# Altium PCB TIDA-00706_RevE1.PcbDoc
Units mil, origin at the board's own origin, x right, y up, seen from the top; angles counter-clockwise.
Board outline 2362.2 x 1377.95 mil, 2 copper layers (Top Layer, Bottom Layer), stack 62 mil thick; 65 components, 35 nets, 166 pads, 49 vias.
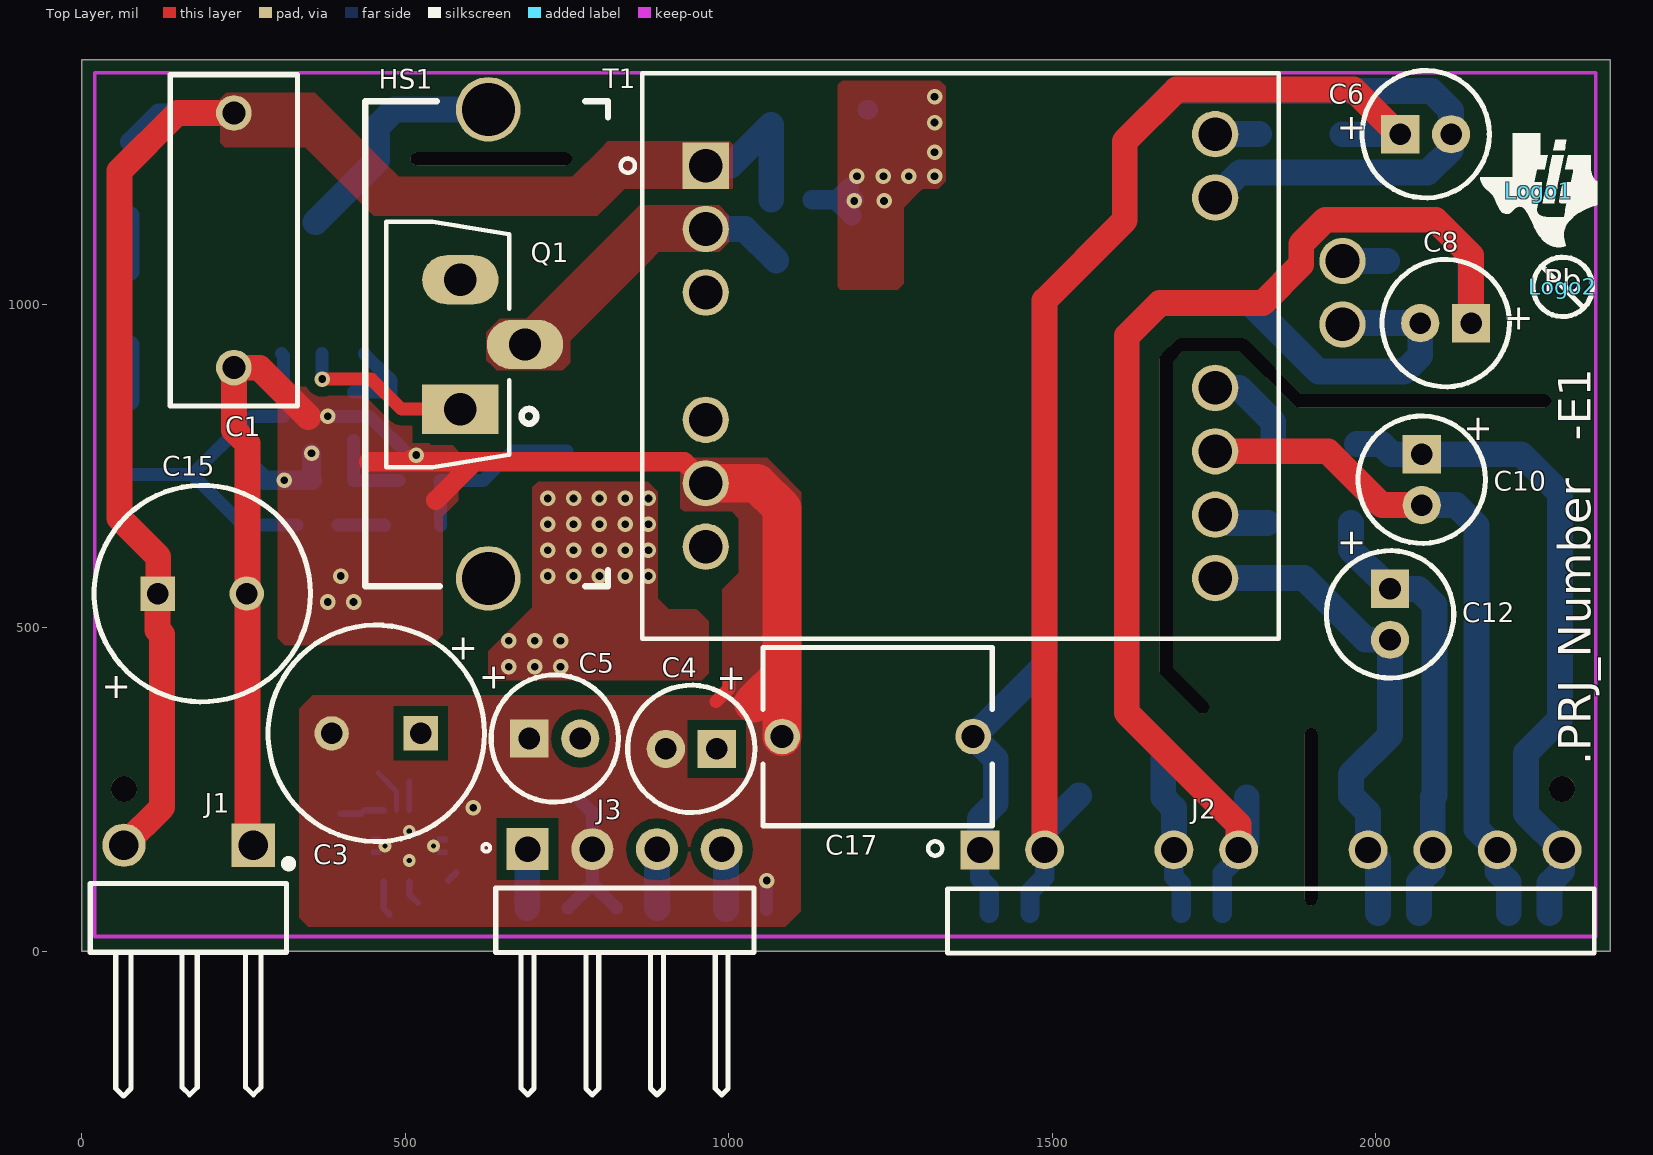
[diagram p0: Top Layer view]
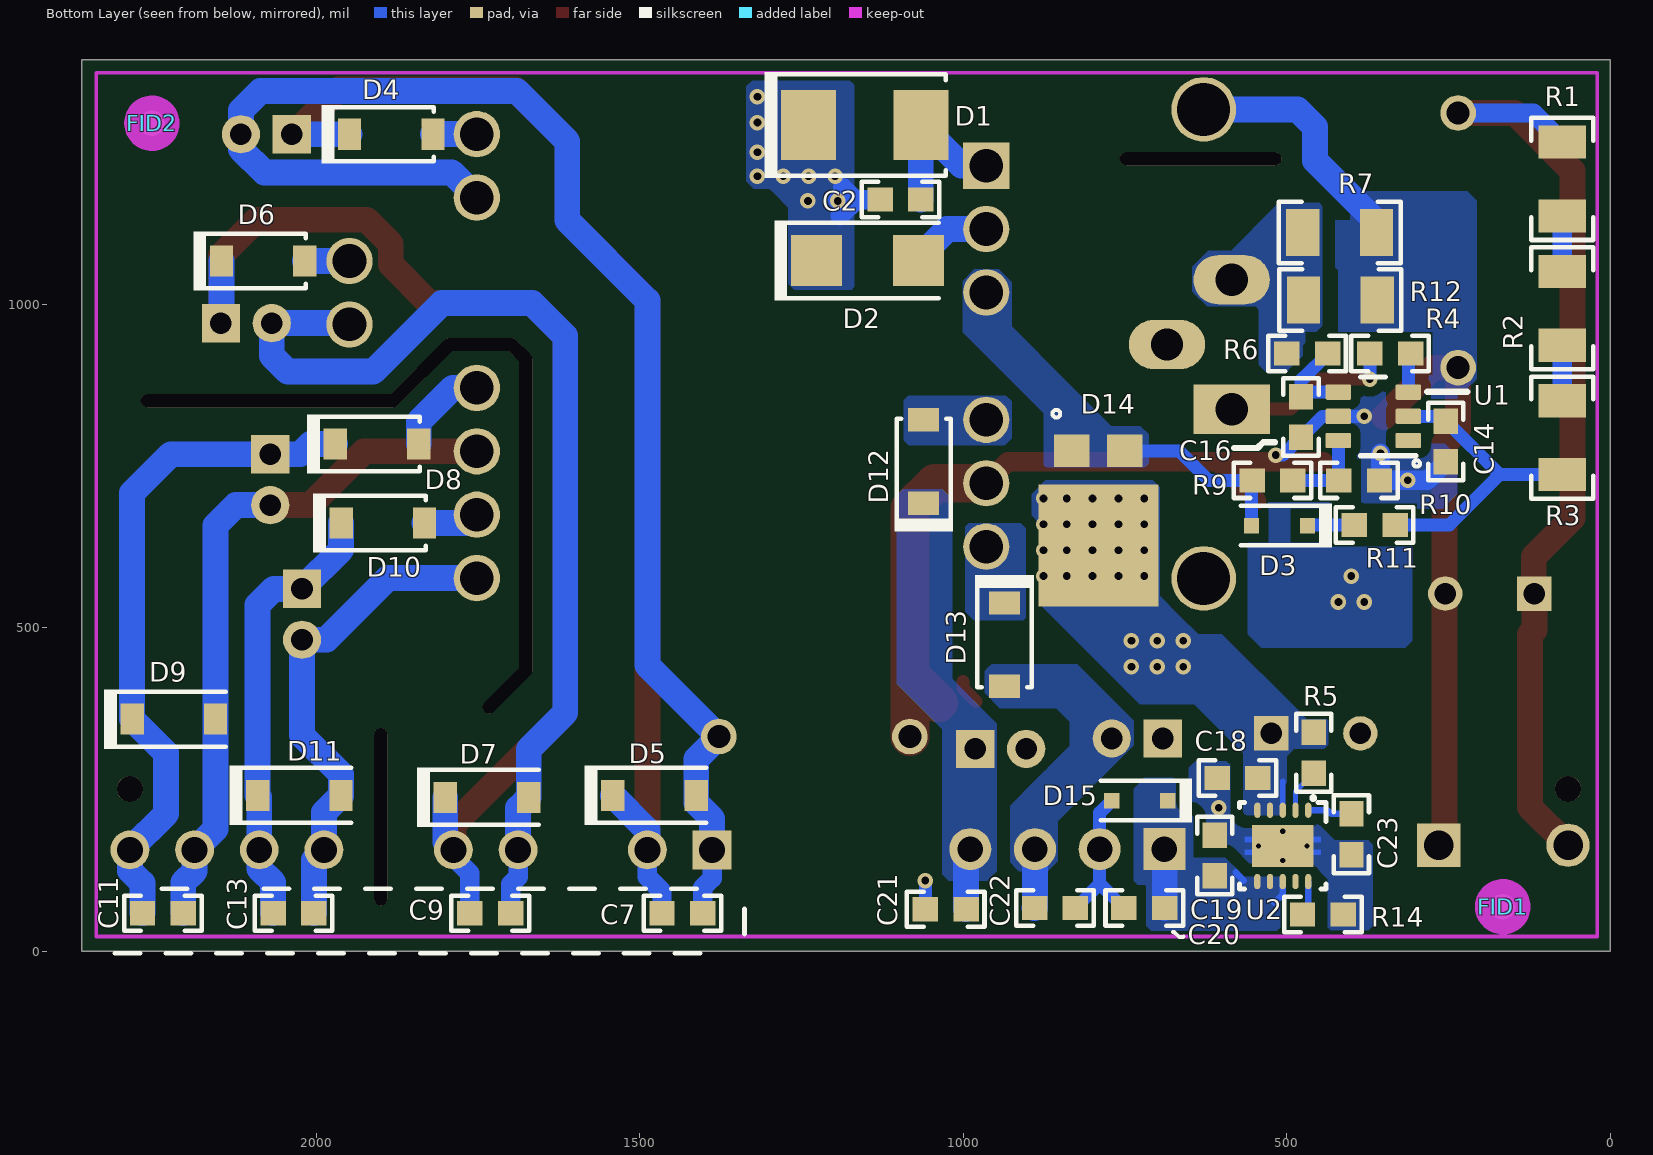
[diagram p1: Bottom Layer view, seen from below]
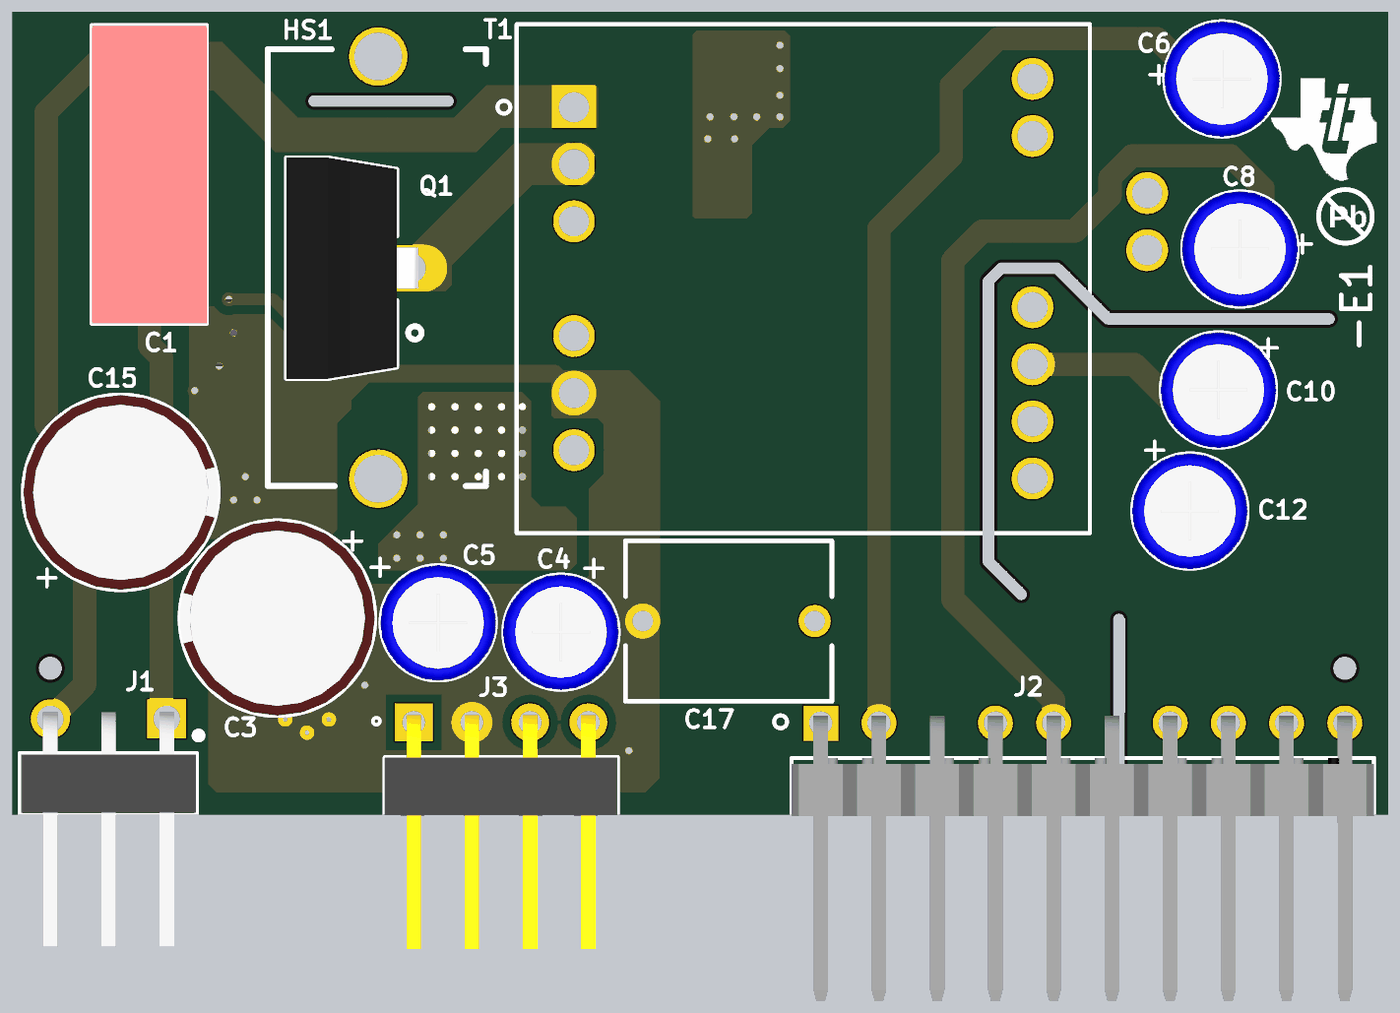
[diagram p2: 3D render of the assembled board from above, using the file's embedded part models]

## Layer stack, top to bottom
Top Solder: solder mask 0.4, Solder Resist, Dk 3.5
Top Layer: signal copper 1.4
Dielectric1: core 59.2, FR-4  High Tg, Dk 4.8
Bottom Layer: signal copper 1.4
Bottom Solder: solder mask 0.4, Solder Resist, Dk 3.5

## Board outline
0,0 0,1377.95 2362.2,1377.95 2362.2,0

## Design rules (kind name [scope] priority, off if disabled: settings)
AcuteAngle [All] p1: minimum=4.50000000000000E+0001 checktracksonly=FALSE
AssemblyTestPointUsage [All] p1: valid=2
Clearance Clearance_1 [ispad vs isvia] p1: gap=8
Clearance Clearance_KEEPOUT [IsKeepOut] p2: gap=3
Clearance Clearance_Poly [InPolygon] p3: gap=15 except(20: Poly-Poly)
Clearance [All] p4: gap=8 except(15: SMDPad-Poly Track-Poly Via-Poly Arc-Poly Fill-Poly THPad-Poly; 20: Poly-Poly)
DiffPairsRouting [All] p1: maxlimit=100 minlimit=10 mostfreqgap=10 toplayer_minwidth=15 toplayer_maxwidth=15 toplayer_prefwidth=15 bottomlayer_minwidth=15 bottomlayer_maxwidth=15 bottomlayer_prefwidth=15 maxuncoupledlength=1000
FabricationTestPointUsage TestPointUsage [All] p1: valid=2 allowmultiple=FALSE
FabricationTestpoint Testpoint [All] p1: side=3 testpointundercomponent=TRUE minsize=40 maxsize=100 preferedsize=60 minholesize=0 maxholesize=40 preferedholesize=32 testpointgrid=1 allowsidetop=TRUE allowsidebottom=TRUE usegrid=TRUE gridtolerance=0.01
FanoutControl Fanout_LCC [IsLCC] p1: bgadir=Out bgaviamode=Centered fanoutstyle=Auto fanoutdirection=Alternating viagrid=1 // Fanout_LCC (Default Rule)
FanoutControl Fanout_BGA [IsBGA] p2: bgadir=Out bgaviamode=Centered fanoutstyle=Auto fanoutdirection=Alternating viagrid=1 // Fanout_BGA (Default Rule)
FanoutControl Fanout_Default [All] p4: bgadir=Out bgaviamode=Centered fanoutstyle=Auto fanoutdirection=Alternating viagrid=1 // Fanout_Default (Default Rule)
FanoutControl Fanout_Small [(CompPinCount < 5)] p5: bgadir=Out bgaviamode=Centered fanoutstyle=Auto fanoutdirection=OutThenIn viagrid=1 // Fanout_Small (Default Rule)
HoleSize [All] p1: absolutevalues=TRUE maxlimit=450 minlimit=8 maxpercent=80.000 minpercent=20.000
MinimumSolderMaskSliver MinimumSolderMaskSliver_Logo [InComponentClass('Logo') vs InComponentClass('Logo')] p1: minsoldermaskwidth=0.7
MinimumSolderMaskSliver [All] p2: minsoldermaskwidth=3.94
PlaneConnect [All] p1: planeconnectstyle=Direct reliefexpansion=10 reliefentries=4 reliefconductorwidth=10 reliefairgap=10
PolygonConnect [All] p1: connectstyle=Direct reliefconductorwidth=10 reliefentries=4 polygonreliefangle="90 Angle" airgapwidth=10
RoutingVias ThermalPadVias [IsVia and InAnyComponent] p1: holewidth=7.87 width=19.68 viastyle="Through Hole" minholewidth=7.87 minwidth=19.68 maxholewidth=12.99 maxwidth=23.62
RoutingVias [All] p2: holewidth=12 width=24 viastyle="Through Hole" minholewidth=10 minwidth=20 maxholewidth=16 maxwidth=32
SilkToBoardRegionClearance [Not ((IsComment or IsDesignator) And (Hide <> 'False')) and not InRegion(1000,500,4000,800)] p1:
SilkToSilkClearance SilkToSilkClearance_Pb-FreeLogo [(HasFootprint('Pb-Free_Overlay_Medium') OR HasFootprint('Pb-Free_Overlay_Small')) vs (HasFootprint('Pb-Free_Overlay_Medium') OR HasFootprint('Pb-Free_Overlay_Small'))] p1: silktosilkclearance=0
SilkToSilkClearance [All] p2: silktosilkclearance=4
SilkToSolderMaskClearance SilkToComonentPadClearance [IsPad and InAnycomponent] p1: minsilkscreentomaskgap=5 clearancetoexposedcopper=TRUE
SilkToSolderMaskClearance "Silk to Solder Mask Opening" [All] p2: minsilkscreentomaskgap=4 clearancetoexposedcopper=FALSE
SolderMaskExpansion [All] p1: expansion=2.5
UnpouredPolygon [All] p1: allowunpoured=FALSE
Width [All] p1: maxlimit=120 minlimit=6 preferedwidth=20 checkconnectedcopper=TRUE
15 further rules are at their usual default settings.

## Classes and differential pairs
component class Header: J1
component class TIDA-00706_Schematics: C1 C2 C3 C4 C5 C6 C7 C8 C9 C10 C11 C12 C13 C14 C15 C16 C17 C18 C19 C20 C21 C22 C23 D1 D2 D3 D4 D5 D6 D7 D8 D9 D10 D11 D12 D13 D14 D15 HS1 J1 J2 J3 Q1 R1 R2 R3 R4 R5 R6 R7 R9 R10 R11 R12 R14 T1 U1 U2
component class AssemblyNote: ZZ2 ZZ3 ZZ4
component class FiducialMark: FID1 FID2
component class TIDA-00706_Hardware: FID1 FID2 Logo1 Logo2 ZZ2 ZZ3 ZZ4
component class Logo: Logo1

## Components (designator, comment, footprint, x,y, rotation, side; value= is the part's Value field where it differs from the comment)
C1 "B32671P6104K" WCAP-FTXX_P10PL20_13x5x11 235,1099 r270 top
C2 "C0603Y472K2RAC7867" 0603 1097,1162 r0 bottom
C3 "EKZN250ELL471MH15D" KZN_800x1150 455,337 r180 top
C4 "25YXJ100M5X11" CAPPR2-5x11 942,313 r180 top
C5 "UPW1E470MDD" CAPPR2-5x11 731,329 r0 top
C6 "25YXJ100M5X11" CAPPR2-5x11 2077,1263 r0 top
C7 "C0603C105K3RACTU" 0603 1434,59 r180 bottom
C8 "25YXJ100M5X11" CAPPR2-5x11 2108,971 r180 top
C9 "C0603C105K3RACTU" 0603 1731,59 r180 bottom
C10 "UPW1E470MDD" CAPPR2-5x11 2071,729 r270 top
C11 "C0603C105K3RACTU" 0603 2237,59 r180 bottom
C12 "25YXJ100M5X11" CAPPR2-5x11 2022,521 r270 top
C13 "C0603C105K3RACTU" 0603 2035,59 r180 bottom
C14 "GRM188R6YA106MA73D" 0603 254,788 r270 bottom
C15 "UVY2W2R2MPD1TD" KZN_800x1150 186,553 r0 top
C16 "GRM1885C1E102JA01D" 0603 478,826 r270 bottom
C17 "CS80ZU2GA222MYNKA" E_900x700x900 1230,332 r0 top locked (schematic designator C35)
C18 "C1608C0G1E472J080AA" 0603 576,268 r0 bottom
C19 "C0603C105K3RACTU" 0603 611,148 r90 bottom
C20 "06033C104JAT2A" 0603 720,67 r0 bottom
C21 "06033C104JAT2A" 0603 1027,65 r0 bottom
C22 "06033C104JAT2A" 0603 858,67 r180 bottom
C23 "GRM1885C1E102JA01D" 0603 400,181 r270 bottom
D1 "SMBJ160A" SMB 1152,1277 r180 bottom
D2 "US1M-13-F" SMA 1148,1068 r180 bottom
D3 "BAS316,115" sod-323 511,658 r0 bottom
D4 "PMEG10020AELRX" SOD-123FL 1884,1263 r180 bottom
D5 "MMSZ4700T1G" SOD-123 1477,241 r180 bottom
D6 "PMEG10020AELRX" SOD-123FL 2082,1067 r180 bottom
D7 "BZT52C9V1-7-F" SOD-123 1736,238 r180 bottom
D8 "PMEG10020AELRX" SOD-123FL 1906,784 r180 bottom
D9 "MMSZ4693T1G" SOD-123 2220,359 r180 bottom
D10 "PMEG10020AELRX" SOD-123FL 1897,662 r180 bottom
D11 "MMSZ5244BT1G" SOD-123 2026,241 r180 bottom
D12 "PMEG10020AELRX" SOD-123FL 1061,757 r90 bottom
D13 "PMEG10020AELRX" SOD-123FL 936,474 r270 bottom
D14 "FSV12100V" TO-277A 791,701.61 r180 bottom
D15 "B0540WS-7" sod-323 727,233 r0 bottom
FID1 "Fiducial" Fiducial10-20 166,69 r180 bottom
FID2 "Fiducial" Fiducial10-20 2254,1280 r180 bottom
HS1 "7173DG" HSINK_7173DG 455,939 r90 top
J1 "PEC03SBAN" Sullins_PEC03SBAN 165,164 r180 top
J2 "PBC10SGBN" SULLINS_PBC10SGBN 1838,47 r180 top locked
J3 "TSW-104-08-G-S-RA" TSW-104-08-G-S-RA 839,158 r0 top (schematic designator J6)
Logo1 "Texas Instruments" TI_Symbol_Overlay_Small 2252,1176 r0 top
Logo2 "Pb-Free Symbol" Pb-Free_Overlay_Small 2289,1027 r0 top
Q1 "AOT7S65L" TO-220_FullPAK_Offset 585,938 r90 top
R1 "CRCW12061M00JNEA" 1206 74,1194 r90 bottom
R2 "CRCW12061M00JNEA" 1206 74,994 r90 bottom
R3 "CRCW12061M00JNEA" 1206 74,794 r90 bottom
R4 "CRCW06030000Z0EA" 0603 340,924 r180 bottom
R5 "CRCW06031M00FKEA" 0603 458,307 r90 bottom
R6 "RC0603FR-07220RL" 0603 468.25,924 r0 bottom
R7 "CRCW12061R24FKEA" 1206 418,1111 r0 bottom
R9 "RC0603FR-0756K2L" 0603 522,728 r0 bottom
R10 "RC0603FR-0725K5L" 0603 388,728 r0 bottom
R11 "CRCW0603100RFKEA" 0603 364,659 r0 bottom
R12 "CRCW12061R24FKEA" 1206 417,1007 r0 bottom
R14 "CRCW060343K2FKEA" 0603 444,57 r0 bottom
T1 "750343154" XFMR_750343154_CUS 1358,920 r0 top locked
U1 "UCC28700DBVR" DBV0006A_N 366,827 r0 bottom
U2 "TPS259241DRCR" DRC0010J 506,163 r270 bottom
ZZ2 "These assemblies are ESD sensitive, ESD precautions shall be observed." AssemblyNote -75,1771.11 r0 top
ZZ3 "These assemblies must be clean and free from flux and all contaminants. Use of no clean flux is not acceptable." AssemblyNote -75,1682.56 r0 top
ZZ4 "These assemblies must comply with workmanship standards IPC-A-610 Class 2, unless otherwise specified." AssemblyNote -75,1594 r0 top

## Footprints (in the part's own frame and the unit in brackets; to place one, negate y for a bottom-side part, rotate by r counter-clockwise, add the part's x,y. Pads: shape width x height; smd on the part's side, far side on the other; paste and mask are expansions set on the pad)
0603 [mm] "0603 from SM-752 data"
  rect 1x0.95 smd: 1(-0.8,0) 2(0.8,0)
  silkscreen extent -1.52,-0.69 1.52,0.69, body extent -0.87,-0.47 0.87,0.47, height 1
1206 [mm] "1206 from SM-752 data"
  rect 1.3x1.85 smd: 1(-1.45,0) 2(1.45,0)
  silkscreen extent -2.4,-1.21 2.4,1.21, body extent -1.7,-0.9 1.7,0.9, height 1.35
AssemblyNote [mil] "Assembly Note"
CAPPR2-5x11 [mm] "Capacitor, Electrolytic, Radial; Body 5 x 11 mm (Dia.xH typ); Pin Spacing 2 mm (typ)"
  rect 1.5x1.5 hole 0.85: 1(-1,0)
  round 1.5 hole 0.85: 2(1,0)
  silkscreen extent -2.5,-2.5 2.5,2.5, body extent -2.53,-2.53 2.53,2.52, height 11.29
DBV0006A_N [mm] "SOT23, 6-Leads, Body 2.9x1.6mm, Pitch 0.95mm, Lead Span 2.8mm, IPC Medium Density"
  rrect17% 1x0.6 smd: 1(-1.375,0.95) 2(-1.375,0) 3(-1.375,-0.95) 4(1.375,-0.95) 5(1.375,0) 6(1.375,0.95)
  silkscreen extent -1.68,-1.55 0.5,1.55, body extent -1.42,-1.46 1.42,1.46, height 1.12
DRC0010J [mm] "SON, 10-Leads, Body 3x3mm, Pitch 0.5mm, Thermal Pad 2.4x1.65mm, TI Recommended"
  oval 0.6x0.24 smd: 1(-1.4,1) 2(-1.4,0.5) 3(-1.4,0) 4(-1.4,-0.5) 5(-1.4,-1) 6(1.4,-1) 7(1.4,-0.5) 8(1.4,0) 9(1.4,0.5) 10(1.4,1)
  rect 1.65x2.4 smd paste-0.825: 11(0,0)
  Top Layer region: 0.135,-1.1 0.365,-1.1 0.365,-1.5 0.135,-1.5
  Top Layer region: -0.135,-1.5 -0.365,-1.5 -0.365,-1.1 -0.135,-1.1
  Top Layer region: -0.135,1.1 -0.365,1.1 -0.365,1.5 -0.135,1.5
  Top Layer region: 0.135,1.5 0.365,1.5 0.365,1.1 0.135,1.1
  silkscreen extent -1.7,-1.7 1.7,1.7, body extent -1.55,-1.55 1.55,1.55, height 1.01
E_900x700x900 [mm] "TH, 2- Leads, Body 9x7mm, Pin Spacing 7.5mm"
  round 1.4 hole 0.9: 1(-3.75,0) 2(3.75,0)
  silkscreen extent -4.5,-3.5 4.5,3.5, body extent -4.49,-3.5 4.49,3.5, height 11.96
Fiducial10-20 [mm]
  round 1 smd mask+0.5: 1(0,0)
  Top Layer keep-out circle w1.178: c0,0 r0.5
HSINK_7173DG [mil] "Aavid"
  round 100 hole 82: 1(-362.5,-173.23) 2(362.5,-173.23)
  silkscreen extent -375,-358 375,17, body extent -375,-358 375,12, height 900
KZN_800x1150 [mm] "TH, 2-Leads, Dia 8mm"
  rect 1.35x1.35 hole 0.85: 1(-1.75,0)
  round 1.35 hole 0.85: 2(1.75,0)
  silkscreen extent -4.25,-4.25 4.25,4.25, body extent -4.22,-4.24 4.24,4.24, height 13.01
Pb-Free_Overlay_Small [mil]
  silkscreen extent -46,-46 46,46
SMA [mm] "Molded Diode, 2-Leads, Body 4.3x2.6mm, IPC Medium Density, based on OnSemi component dimensions and land pattern"
  rect 2x2 smd: 1(-2,0) 2(2,0)
  silkscreen extent -3.66,-1.57 2.79,1.57, body extent -2.6,-1.3 2.6,1.3, height 2.42
SMB [mil] "Molded Diode, 2-Leads, Body 5.4x3.6mm, IPC Medium Density, based on OnSemi component dimensions"
  rect 85x107.99 smd: 1(-87.01,0) 2(87.01,0)
  silkscreen extent -155,-82 125,82, body extent -106,-71 106,71, height 91
SOD-123 [mm] "On Semi recommended land pattern"
  rect 0.915x1.22 smd: 1(-1.637,0) 2(1.637,0)
  silkscreen extent -2.74,-1.17 2.03,1.17, body extent -1.93,-0.9 1.93,0.9, height 1.35
SOD-123FL [mm] "Copied from SOD-123"
  rect 0.915x1.22 smd: 1(-1.637,0) 2(1.637,0)
  silkscreen extent -2.74,-1.16 1.68,1.16, body extent -1.9,-0.9 1.9,0.9, height 1
sod-323 [mm] "NXP recommended land pattern"
  rect 0.6x0.6 smd paste-0.05: 1(-1.1,0) 2(1.1,0)
  silkscreen extent -2.06,-0.86 1.53,0.86, body extent -1.3,-0.67 1.3,0.68, height 1.1
SULLINS_PBC10SGBN [mil] "CONN,MALE-10PIN 2.54MM PITCH,SINGLEROW,SULLINS"
  rect 60x60 / inner round 60 / far side rect 60x60 hole 40: 1(450,-109.84)
  round 60 hole 40: 2(350,-109.84) 4(150,-109.84) 5(50,-109.84) 7(-150,-109.84) 8(-250,-109.84) 9(-350,-109.84) 10(-450,-109.84)
  round 0 all layers, no hole mask+0: 3(250,-109.84) 6(-50,-109.84)
  silkscreen extent -500,-123 530,50, body extent -500,-122 500,368, height 142
Sullins_PEC03SBAN [mm] "Sullins"
  rect 1.7x1.7 hole 1.16: 1(-2.54,0)
  round 0 all layers, no hole mask+0: 2(0,0)
  round 1.7 hole 1.16: 3(2.54,0)
  silkscreen extent -4.07,0.58 3.86,9.85, body extent -3.81,-0.29 3.81,9.94, height 3.56
TI_Symbol_Overlay_Small [mil]
  silkscreen extent -90,-88 91,88
TO-220_FullPAK_Offset [mil] "Infineon  PG-TO220-3-31"
  rect 76x118.11 hole 50: 1(-100,0)
  oval 76x118.11 hole 50: 2(0,-100) 3(100,0)
  silkscreen extent -190,-75 190,115, body extent -190,-112 190,115, height 902
TO-277A [mm] "Vishay"
  rect 1.4x1.27 smd: 1(-1.04,1.83) 2(1.04,1.83)
  rect 4.72x4.8 smd: 3(0,-1.883)
  silkscreen extent -1.8,3.13 -1.5,3.44, body extent -2.35,-4.2 2.4,2.45, height 1.2
TSW-104-08-G-S-RA [mm] "Samtec Right Angle Header"
  rect 1.65x1.65 hole 1: 1(-3.81,0)
  round 1.65 hole 1: 2(-1.27,0) 3(1.27,0) 4(3.81,0)
  silkscreen extent -5.59,-9.65 5.08,0.2, body extent -5.08,-9.91 5.08,0.32, height 3.05
WCAP-FTXX_P10PL20_13x5x11 [mm] "TH, 2-Leads, Body 13x5mm, Pitch 10mm"
  round 1.4 hole 0.9: 1(-5,0) 2(5,0)
  silkscreen extent -6.5,-2.5 6.5,2.5, body extent -6.5,-2.5 6.5,2.5, height 11
XFMR_750343154_CUS [mm] "TRANSFORMER, 2.49 MM PITCH, 14-PIN, 16 MM HEIGHT"
  rect 1.82x1.82 / inner round 1.82 / far side rect 1.82x1.82 hole 1.32: 1(-10,7.48)
  round 1.82 hole 1.32: 2(-10,4.99) 3(-10,2.5) 4(-10,-2.5) 5(-10,-4.99) 6(-10,-7.48) 7(10,-8.715) 8(10,-6.225) 9(10,-3.735) 10(10,-1.245) 11(15,1.245) 12(15,3.735) 13(10,6.225) 14(10,8.715)
  silkscreen extent -13.34,-11.1 12.5,11.1, body extent -12.5,-11.1 12.5,11.1, height 16

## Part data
C1: library part 890334023006, "CAP, Film, 0.1 µF, 630 V, +/- 10%, TH"
C2: library part 06031C472JAT2A, "CAP CER 4700PF 200V X7R 0603"
C3: library part EKZN250ELL271MHB5D, "CAP, AL, 470 µF, 25 V, +/- 20%, 0.075 ohm, TH"
C4 C6 C8 C12: library part UVR1V100MDD1TA, "CAP, AL, 100 µF, 25 V, +/- 20%, TH"
C5 C10: library part UVR1V100MDD1TA, "CAP, AL, 47 µF, 25 V, +/- 20%, TH"
C7 C9 C11 C13: library part C0603C105K8PACTU, "CAP CER 1UF 25V X7R 0603"
C14: library part GRM188R6YA106MA73, "CAP, CERM, 10 µF, 35 V, +/- 20%, X5R, 0603"
C15: library part EKZN250ELL271MHB5D, "CAP ALUM 2.2UF 20% 450V RADIAL"
C16 C23: "CAP, CERM, 1000 pF, 25 V, +/- 5%, C0G/NP0, 0603"
C17: library part DE6E3KJ222MN3A, "CAP CER 2200PF 300VAC 20% RADIAL"
C18: library part 0603ZD475KAT2A, "CAP, CERM, 4.7 µF, 25 V, +/- 10%, 0603"
C19: "CAP, CERM, 1 µF, 25 V, +/- 10%, X7R, 0603"
C20 C21 C22: "CAP, CERM, 0.1 µF, 25 V, +/- 5%, X7R, 0603"
D1: library part SMBJ160A-13-F, "TVS DIODE 160VWM 259VC SMB"
D2: "Diode, Ultrafast, 1000 V, 1 A, SMA"
D3: "Diode, Ultrafast, 100V, 0.25A, SOD-323"
D4 D6 D8 D10 D12 D13: library part MBR1H100SFT3G, "DIODE SCHOTTKY 100V 2A SOD2123"
D5: "Diode, Zener, 13 V, 500 mW, SOD-123"
D7: library part BZT52B9V1-HE3-08, "DIODE ZENER 9.1V 500MW SOD123"
D9: "Diode, Zener, 7.5 V, 500 mW, SOD-123"
D11: library part MMSZ4700T1G, "Diode, Zener, 14 V, 500 mW, SOD-123"
D14: library part SS5P10-M3/86A, "DIODE SCHOTTKY 100V 12A TO277-3"
D15: "Diode, Schottky, 40 V, 0.5 A, SOD-323"
FID1 FID2: "Fiducial mark.  There is nothing to buy or mount."
HS1: "Heat Sink, TO-220 Vertical"
J1: "Header, 100mil, 3x1, Tin, R/A, TH"
J2: "CONNECTOR, HEADER, 2.54MM PITCH, 10 POS, RIGHT ANGLE, TH, ROHS"
J3: "Header, 100mil, 4x1, Gold, R/A, TH"
Logo1: library part TI_Logo, "Texas Instrument Corporate Signature"
Logo2: library part Pb-Free
Q1: library part IPA60R385CP, "MOSFET, N-CH, 650 V, 7 A, TO-220"
R1 R2 R3: "RES, 1.0 M, 5%, 0.25 W, 1206"
R4: "RES, 0, 5%, 0.1 W, 0603"
R5: "RES, 1.00 M, 1%, 0.1 W, 0603"
R6: "RES, 220, 1%, 0.1 W, 0603"
R7 R12: "RES, 1.24, 1%, 0.25 W, 1206"
R9: library part CRCW060310K0FKEA, "RES SMD 56.2K OHM 1% 1/10W 0603"
R10: library part CRCW06034K64FKEA, "RES SMD 25.5K OHM 1% 1/10W 0603"
R11: "RES, 100, 1%, 0.1 W, 0603"
R14: "RES, 43.2 k, 1%, 0.1 W, 0603"
U1: "Constant-Voltage, Constant-Current Controller With Primary-Side Regulation, DBV0006A"
U2: "12-V eFuse with Over Voltage Protection and Blocking FET Control, DRC0010J"
ZZ2 ZZ3 ZZ4: library part AssemblyNote

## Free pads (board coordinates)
  round 40 hole 40 unplated mask+5: 0(65,251) 0(2288,251)
  oval 20x500 hole 20 slot 500 at 90 deg unplated mask+5: 1(1676,676)
  oval 20x50 hole 20 slot 50 at 45 deg unplated rot 135 mask+5: 1(1687,927)
  oval 20x100 hole 20 slot 100 at 135 deg unplated rot 45 mask+5: 1(1704,406)
  oval 115x20 hole 20 slot 115 at 0 deg unplated mask+5: 1(1746,938)
  oval 20x135 hole 20 slot 135 at 135 deg unplated rot 45 mask+5: 1(1837,895)
  oval 400x20 hole 20 slot 400 at 0 deg unplated mask+5: 1(2071,851)
  oval 20x274.02 hole 20 slot 274.02 at 90 deg unplated mask+5: 2(1900,208)
  oval 250x20 hole 20 slot 250 at 0 deg unplated mask+5: 4(633,1225)

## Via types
v1: diameter 24, hole 12, Top Layer to Bottom Layer, tented both sides, 45 vias
v2: diameter 19.68, hole 7.87, Top Layer to Bottom Layer, 4 vias

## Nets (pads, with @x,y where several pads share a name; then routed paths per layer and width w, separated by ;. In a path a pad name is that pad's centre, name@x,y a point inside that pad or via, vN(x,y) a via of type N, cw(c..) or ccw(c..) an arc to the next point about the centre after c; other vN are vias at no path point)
7.2V_ISO/0.1A: C8.1 C9.1 D6.1 D7.1 J2.5 | length 1909.9
  Top Layer w40: J2.5 1788,196 1615,369 1615,951 1666,1002 1825,1002 1884.73,1061.73 1884.73,1093.6 1922,1130.87 2092,1130.87 2147.37,1075.5 C8.1
  Bottom Layer w30: C9.1 1762.5,120.5 1788,146 J2.5
  Bottom Layer w40: J2.5 1800.47,169.31 D7.1 ; D6.1 2146.47,971.9 C8.1
+5V/0.2A: C4.1 C21.1 D12.1 J3.4 | length 95.7
  Bottom Layer w40: J3.4 995.5,151.5 C21.1
+6V_ISO/0.05A: C10.1 C11.1 D8.1 D9.1 J2.10 | length 1047.8
  Bottom Layer w40: D8.1 2009,784 2024.63,768.37 C10.1 2224.63,768.37 2284.47,708.53 D9.1 2232,306.53 2232,212.84 J2.10 2288,125 2268.5,105.5 C11.1
+11V_ISO/0.2A: C6.1 C7.1 D4.1 D5.1 J2.2 | length 1939
  Top Layer w40: J2.2 1488,1006 1612,1130 1612,1252 1692,1332 1965.63,1332 C6.1@2037.63,1260
  Bottom Layer w30: C7.1 1465.5,92.5 1488,115 J2.2
  Bottom Layer w40: J2.2 1488,187.53 D5.1 ; D4.1 2034.63,1263 C6.1@2037.63,1260
+12V/1.5A: C19.1 C20.1 D15.1 J3.1 U2.6 U2.7 U2.8 | length 147.9
  Bottom Layer w10: U2.8 506,88 519,75 ; 566,109 579,122
  Bottom Layer w40: C20.1 688.5,157.5 J3.1
+12V_ISO/0.2A: C12.1 C13.1 D10.1 D11.1 J2.8 | length 691.9
  Bottom Layer w40: D10.1 1961.47,620.9 C12.1 2065.63,560.37 2090.47,535.53 D11.1 2088,238.53 J2.8 2088,128 2066.5,106.5 C13.1
+12V_M: C3.1 C18.1 D14.3 R5.2 U2.3 U2.4 U2.5 | length 44.9
  Bottom Layer w8: U2.3 506,263
  other v1: 660,440 700,440 740,440 660,480 700,480 740,480 720,580 760,580 800,580 840,580 875.65,580 720,620 760,620 800,620 840,620 875.65,620 720,660 760,660 800,660 840,660 875.65,660 720,700 760,700 800,700 840,700 875.65,700
-7.2V/0.05A: C5.2 C22.1 D13.2 J3.3 | length 91.2
  Bottom Layer w40: J3.3 889,67.5 C22.1
NetC2_2: C2.2 D1.1 D2.1 | length 128.6
  Bottom Layer w30: C2.2 1165,1162 ; 1186,1180 1168,1162 ; 1190,1137 1165,1162 ; v1@1194,1162 1168,1162 ; D1.1@1213.5,1301 D1.1@1215.74,1301 ; 1165,1162 1168,1162
  other v1: 1194,1160 1240,1160 1198,1198 1239,1198 1278,1198 1318,1198 1318,1235 1318,1281 1318,1321
NetC16_1: C16.1 R6.1 U1.4 | length 144.8
  Bottom Layer w20: U1.4 471.09,864.4 C16.1 478,882.76 473.46,887.3 472.61,887.3 436.76,923.15 R6.1
NetC23_1: C23.1 U2.1 | length 69
  Bottom Layer w10: C23.1 431.38,212.5 437,218.12 U2.1
NetD2_2: D2.2 Q1.2 T1.2 | length 137
  Bottom Layer w30: T1.2@956.3,1101.46 T1.2@964.3,1101.46
  Bottom Layer w40: T1.2 1024.8,1116.46 D2.2@1073.26,1068
NetD3_1: D3.1 R11.2 | length 72.6
  Bottom Layer w20: R11.2 466.69,659 D3.1
NetD3_2: D3.2 D14.1 D14.2 R9.2 T1.3 | length 285.8
  Bottom Layer w20: D3.2 554.31,727.19 R9.2 620.67,728 666.33,773.66 D14.2
NetD4_2: D4.2 T1.14 | length 67.9
  Bottom Layer w40: T1.14 1819.42,1263.11 D4.2
NetD6_2: D6.2 T1.12 | length 69
  Bottom Layer w40: T1.12 D6.2 D6.2
NetD8_2: D8.2 T1.10 | length 146.1
  Bottom Layer w40: T1.10 1789.02,870.98 1841.53,818.47 D8.2
NetD10_2: D10.2 T1.8 | length 86.2
  Bottom Layer w40: T1.8 1764.62,662 D10.2
NetD12_2: D12.2 T1.4
NetD13_1: D13.1 T1.6
NetQ1_1: Q1.1 R4.1 | length 272.3
  Top Layer w20: v1(371.5,884.5) 447.5,884.5 494,838 Q1.1
  Bottom Layer w20: v1(371.5,884.5) R4.1
NetQ1_3: Q1.3 R6.2 R7.2 R12.2
NetR1_1: R1.1 R2.2 | length 85.8
  Bottom Layer w30: R2.2 R1.1
NetR2_1: R2.1 R3.2 | length 85.8
  Bottom Layer w30: R3.2 R2.1
NetR4_2: R4.2 U1.3 | length 61
  Bottom Layer w20: R4.2 311.86,920.64 U1.3
NetR5_1: R5.1 U2.2 | length 69.1
  Bottom Layer w8: R5.1 486.31,247.19 U2.2
NetR14_2: R14.2 U2.10 | length 54.6
  Bottom Layer w10: U2.10 466.63,65.87 R14.2
PGND: C1.2 C3.2 C4.2 C5.1 C14.2 C15.2 C16.2 C17.1 C18.2 C19.2 C20.2 C21.2 C22.2 C23.2 D15.2 HS1.2 J1.1 J3.2 R7.1 R10.1 R12.1 R14.1 T1.5 U1.5 U2.11 | length 3093.2
  Top Layer w20: v1@506.54,764.98 514.98,764.98 v1(517,767) ; 980,386 1000,406 1000,417
  Top Layer w30: 443,757 607,757 ; 547,697 607,757 ; T1.5 930.84,757 607,757
  Top Layer w40: J1.1 255.9,173.1 255.9,785 235,805.9 C1.2 274.37,902.15 350,826.52 350,826
  Top Layer w60: T1.5 1043.46,723.54 1082.36,684.64 1082.36,428.36 ; 1038,384 1082.36,428.36 ; C17.1 1082.36,428.36
  Bottom Layer w20: v1(380,827) U1.5 444.65,827 477.15,794.5 C16.2 505.5,767 v1(517,767) ; C20.2 789,104.5 ; D15.2 789,214.31 J3.2 789,104.5 ; C22.2 789,104.5 ; C21.2 v1(1058.5,109.5)
  Bottom Layer w30: C14.2 282.5,728 v1(313,728) R10.1 355,729.5 v1(355,770.07)
  Bottom Layer w40: R7.1@360.91,1127 456.46,1222.54 456.46,1274.46 483.5,1301.5 HS1.2
  other v1: 605,222 380,540 420,540 400,580
  other v2: 506,140.36 468.6,163 543.4,163 506,185.64
PGND2: C12.2 C13.2 D11.2 J2.7 T1.7 | length 774.8
  Bottom Layer w40: T1.7 1889.11,576.89 1984.37,481.63 C12.2 2022,334 1961.53,273.53 D11.2 1988,214.53 J2.7 2003.5,141.34 C13.2
PGND3: C10.2 C11.2 D9.2 J2.9 T1.9 | length 1071.4
  Top Layer w40: T1.9 1926.05,772.95 2009.37,689.63 C10.2
  Bottom Layer w40: C10.2 2124.37,689.63 2155.53,658.47 D9.2 2155.53,189.31 J2.9 2188,124 2205.5,106.5 C11.2
SGND1: C8.2 C9.2 D7.2 J2.4 T1.11 | length 1627.1
  Bottom Layer w30: J2.4 1688,115 1699.5,103.5 C9.2
  Bottom Layer w40: J2.4 1688,221.53 D7.2 1671.53,312.47 1615,369 1615,951 1666,1002 1806,1002 1912,896 2044,896 2068.63,920.63 C8.2 1950.54,971 T1.11
SGND2: C6.2 C7.2 C17.2 D5.2 J2.1 T1.13 | length 2325.2
  Bottom Layer w30: J2.1 1388,113 1402.5,98.5 C7.2
  Bottom Layer w40: J2.1 1388,205 1412.53,229.53 D5.2 1412.53,297.11 C17.2 1488,442.36 1488,1006 1612,1130 1612,1252 1690,1330 2086,1330 2116.37,1299.63 C6.2 2116.37,1240.09 2080.28,1204 1790.62,1204 T1.13
VDCBUS: C1.1 C2.1 C15.1 D1.2 J1.3 R1.2 T1.1 | length 1737.7
  Top Layer w40: J1.3 124,223 124,490 117.1,496.9 C15.1 ; C15.1@118.1,553 118.1,609.9 58,670 58,1206 147.85,1295.85 C1.1
  Bottom Layer w30: R1.2 118.76,1295.85 C1.1 ; T1.1@956.3,1199.49 T1.1@964.3,1199.49
  Bottom Layer w40: T1.1 1002.48,1214.49 D1.2 1065.5,1276.49 C2.1
VDD: C14.1 R3.1 R11.1 U1.2 | length 469.4
  Bottom Layer w20: R3.1 170.57,736.91 ; U1.2 261.5,827 C14.1 253.15,819.5 170.57,736.91 ; R11.1 248.48,659 170.57,736.91
VS: R9.1 R10.2 U1.6 | length 132.9
  Bottom Layer w20: U1.6 420.13,728.64 R10.2 R9.1
pads on no net: FID1.1 FID2.1 HS1.1 J1.2 J2.3 J2.6 U1.1 U2.9

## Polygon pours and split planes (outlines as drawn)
NetC2_2 on Top Layer "Bottom Layer-No Net 1" (solid, remove dead copper, pour order 36): 1270,1032 1270,1149.5 1293,1172.5 1299.5,1179 1324,1179 1335,1190 1335,1337 1326,1346 1247,1346 1175,1346 1170,1341 1168,1339 1168,1212 1168,1027 1172,1023 1261,1023
PGND on Top Layer "Top Layer-No Net" (solid, remove dead copper, pour order 38): 925,745 925,695 925,685 930,680 980,680 1004.5,680 1015.5,669 1015,668.5 1015,620 1015,585 990,560 990,370 1104,370 1112,378 1112,480 1112,710 1073,749 1059,763 975,763 936.84,763 930.84,757 925,751.16
NetD2_2 on Top Layer "Bottom Layer-No Net 1" (solid, remove dead copper, pour order 34): 646,978 687,978 703,994 862,1153 930,1153 985,1153 1000,1138 1000,1096 985,1081 926,1081 892,1081 877,1066 755,944 755,933 755,910 743,898 718,898 641,898 634,905 625,914 625,916 625,957 633,965
VDCBUS on Top Layer "Bottom Layer-No Net 1" (solid, remove dead copper, pour order 21): 236,1327 223,1327 218,1322 214,1318 214,1301 214,1250 221,1243 268,1243 345,1243 424,1164 451,1137 697,1137 797,1137 818,1158 836,1176 839,1179 1005,1179 1006,1180 1006,1205 1006,1247.46 1002.46,1251 1001.46,1252 977,1252 813,1252 801,1240 758,1197 489.73,1197 414,1273 360,1327 240,1327
PGND on Top Layer "Bottom Layer-No Net 1" (solid, remove dead copper, pour order 27): 303,827.35 303,483.33 305,481.33 313.33,473 338,473 542,473 558,489 558,532 558,672.5 572.5,687 582,696.5 582,732 582,773 573,782 540,782 518,804 510,812 510,851 488.3,872.7 367,873 319.08,873 303,856.92
+12V_M on Top Layer "Bottom Layer-No Net 1" (solid, remove dead copper, pour order 29): 696.51,716 696,715.49 696,534 696,532 672,508 628,464 628,442 628,428 637,419 958,419 969,430 969,456 969,510 954,525 950,529 908,529 907,529 897,539 890.5,545.5 890.5,562 890.5,710.38 880.36,720.53 874.88,726 824,726 705.51,726 696.51,717
PGND on Top Layer "Bottom Layer-No Net 1" (solid, remove dead copper, pour order 24): 336,375 336,284 336,52 350,38 617,38 723,38 1087,38 1108,59 1111,62 1111,227 1111,357 1100,368 1072,396 789,396 357,396
NetD3_2 on Bottom Layer "Top Layer-No Net 2" (solid, remove dead copper, pour order 37): 719,748 865.87,748 871.65,748 875.65,752 875.65,786.35 875.65,831.65 1001,957 1001,1023 1001,1036 983,1054 945,1054 925,1034 925,966 839,880 771,812 726,812 714,800 713,799 713,763 713,754 716,751
+5V/0.2A on Bottom Layer "Bottom Layer-No Net 1" (solid, remove dead copper, pour order 25): 1034,714 1093,714 1103,704 1103,414 1032,343 1032,119 1022,109 992,109 963,109 957,115 948,124 948,352 952,356 1017,421 1017,699 1032,714
NetD12_2 on Bottom Layer "Bottom Layer-No Net 1" (solid, remove dead copper, pour order 28): 952,859 1010,859 1085,859 1092,852 1092,830 1092,798 1092,790 1086,784 1084,782 966,782 936,782 926,792 925,793 925,822 925,850 934,859
NetD13_1 on Bottom Layer "Bottom Layer-No Net 1" (solid, remove dead copper, pour order 30): 926,662 975,662 991,662 1000,653 1003,650 1003,627 1003,531 992,520 984,512 942,512 907,512 903,516 903,654 911,662
NetC2_2 on Bottom Layer "Bottom Layer-No Net 1" (solid, remove dead copper, pour order 35): 1270,1032 1270,1149.5 1293,1172.5 1299.5,1179 1324,1179 1335,1190 1335,1337 1326,1346 1247,1346 1175,1346 1170,1341 1168,1339 1168,1212 1168,1027 1172,1023 1261,1023
+12V/1.5A on Bottom Layer "Top Layer-NetL_1" (solid, remove dead copper, pour order 22): 500,122 499,121 499,100 499,89 499,48 515,32 562,32 627,32 641,32 709,32 736.48,59.48 736.48,191.86 736.48,251.52 720,268 667,268 641.52,242.52 641.52,188 641.52,155.52 636,150 632,146 618,146 596,146 572,122 501,122
+12V_M on Bottom Layer "Top Layer-NetL_1" (solid, remove dead copper, pour order 20): 696.51,717.36 696.51,549.51 666,519 637,490 600,490 480,370 469,359 454,359 438,359 437,358 436,357 436,332 436,319 440,315 442,313 456,313 488.89,313 491.7,310.19 500,301.89 500,300 500,209 505,204 512,204 557,204 561,208 567,214 567,229.93 567,306 598,337 643,382 723,382 727,382 890.5,545.5 894,549 894,570 894,706.88 872.88,728 780,728 707.15,728 696.51,717.36
NetQ1_3 on Bottom Layer "Top Layer-NetL_1" (solid, remove dead copper, pour order 31): 445,1152 445,1101 445,967 448,964 456,956 466,946 475,937 475,917 475,902 480,897 502.25,896.73 532.73,896.73 543,907 543,936 543,988 543,992 548,997 569,997 623,997 642,1016 646,1020 646,1058 621,1083 587,1083 586,1083 519,1150 512,1157 452,1157 450,1157
PGND on Bottom Layer "Top Layer-NetL_1" (solid, remove dead copper, pour order 26): 470,200 454,200 448.16,194.16 426,172 374,172 367,165 367,136.42 367,39 372,34 373,33 399,33 431.83,33 432.5,33.66 435.35,36.51 436.61,36.51 436.61,111.22 448.05,122.66 449.39,124 468,124 559,124 576,141 586,151 635,151 639.52,151 641.52,153 639.54,154.98 639.54,209.02 639.54,214.54 645,220 651,226 651,236 651,284 645,290 640.8,294.2 621,294.2 593.2,294.2 587.39,288.39 582,283 582,273 582,213 569,200 471,200
PGND on Bottom Layer "Bottom Layer-No Net 1" (solid, remove dead copper, pour order 23): 237,926 236,925 236,875 236,550 317,469 412,469 539,469 573,503 589,519 629,519 645,519 671,545 679,553 679,627 679,697 659,717 634,742 510,742 489,742 450,781 420,811 420,925 420,1053 425,1058 432,1065 432,1095 432,1124 426,1130 393,1130 272,1130 237,1095
PGND on Bottom Layer "Top Layer-NetL_1" (solid, remove dead copper, pour order 33): 402,1166 402,1097 402,981 389,968 380.36,959.36 357.94,959.36 274.36,959.36 270,955 270,921 270,889 253,872 251,870 233,870 221,870 208,883 206,885 206,917 206,1160 221,1175 280,1175 393,1175
-7.2V/0.05A on Bottom Layer "Bottom Layer-No Net 1" (solid, remove dead copper, pour order 32): 736,356 736,319 854,201 854,166 854,139 862,131 869,124 887,124 914,124 918,128 928,138 928,155 928,225 889,264 835,318 835,352 835,355 843,363 856,376 874,376 949,376 964,391 967,394 967,428 967,433 962,438 956,444 923,444 824,444

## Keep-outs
Keep-Out Layer:
  lines w6: 20,23 20,1358 2340,1358 2340,23 20,23

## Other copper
Top Layer:
  text ".Layer_Name" at 257,-1457.49 h60
Bottom Layer:
  pour cut-out: 736.48,109.48 730,103 719.11,103 716.81,100.7 716.81,95.7 731.48,95.7 736.48,100.7
  pour cut-out: 572,122 568,118 567.02,118 567.02,122
  pour cut-out: 237,639 294.43,639 306,627.43 306,467.5 300.5,462 233,462 233,635
  pour cut-out: 560,640 580,620 580,500 560,480
  text ".Layer_Name" at 257,-1457.49 h60

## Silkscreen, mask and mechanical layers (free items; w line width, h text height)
Top Overlay:
  circle w10: c691,827 r11.4
  text "-E1" at 2332,789 h50 r90
  text ".PRJ_Number" at 2332,288 h50 r90
  text ".Layer_Name" at 257,-1457.49 h60
Bottom Overlay:
  circle w6: c459,237 r3
  circle w6: c299,754 r5
  lines w6: 659,23 660,22 666,22 674,30 676,30
  lines w10: 221,865 283,865 ; 518,787 536,787 545,778 581,778
  text ".Layer_Name" at 257,-1457.49 h60
Top Paste:
  text ".Layer_Name" at 257,-1457.49 h60
Bottom Paste:
  text ".Layer_Name" at 257,-1457.49 h60
Top Solder:
  text ".Layer_Name" at 257,-1457.49 h60
  text ".Layer_Name" at 257,-1457.49 h60
Bottom Solder:
  text ".Layer_Name" at 257,-1457.49 h60
M1 Board Outline:
  the board outline again, w10
M2 Board Dimensions:
  rectangle: -195,-999 180,-874
  rectangle: -320,-874 -195,-749
  lines w7: -320,-874 680,-874 ; -195,-999 -195,-749 ; -70,-999 -70,-749 ; 180,-999 180,-749 ; 430,-999 430,-749 ; -320,-999 -320,-749 680,-749 680,-999 -320,-999
M3 3D STEP Top:
  text ".Layer_Name" at 257,-1457.49 h60
M4 3D STEP Bottom:
  text ".Layer_Name" at 257,-1457.49 h60
M5 Assembly Top:
  circle w10: c617,824 r9.22
  circle w10: c260,78 r10
  circle w6: c689,158 r8
  circle w6: c689,158 r8
  lines w10: -612,-1529.17 5988,-1529.17 ; -612,-1325.83 5990,-1325.83 ; -612,-1122.5 -612,-1732.5 3393,-1732.5 5990,-1732.5 5990,-1122.5 -611.5,-1122.5 -611.5,-1732.5 964,-1732.5 ; 1853,-1732.5 1853,-1122.5 ; 3120,-1325.83 3120,-1122.5 ; 3960,-1325.83 3960,-1122.5 ; 4582,-1739 4582,-1536.17
  text "C6" at 2028,1249 h30
  text "COMPONENTS MARKED 'DNP' SHOULD NOT BE POPULATED." at 833.5,-917.5 h60
  text "ASSEMBLY VARIANT:" at 833,-1033 h60
  text ".VariantName" at 1869,-1033 h60
  text "PCB VIEWED FROM TOP SIDE" at -548.5,-1254.67 h60
  text "BOARD #:" at 1928,-1254.67 h60
  text ".PRJ_Number" at 2473.5,-1254.67 h60
  text "REV:" at 3318,-1254.67 h60
  text ".PCB_Rev" at 3609.5,-1254.67 h60
  text "SVN REV:" at 4156,-1254.67 h60
  text ".VersionControl_RevNumber" at 4662,-1254.67 h60
  text ".Layer_Name" at 276,-1456 h50
  text "TID #:" at 1928,-1458 h60
  text ".TID" at 2473.5,-1458 h60
  text "PLOT NAME =" at -548.5,-1663.34 h60
  text ".plot_File_Name" at 257,-1663.34 h60
  text "GENERATED    :" at 1930,-1663.34 h60
  text ".Print_Date" at 2799.5,-1663.34 h60
  text ".Print_Time" at 3528.5,-1663.34 h60
  text "TEXAS INSTRUMENTS" at 4793,-1663.34 h60
M6 Assembly Bottom:
  lines w10: -612.5,-1326.33 5989.5,-1326.33 ; -610.5,-1529.67 5989.5,-1529.67 ; 795.5,-1739.5 795.5,-1536.67 ; 1417.5,-1326.33 1417.5,-1123 ; 2257.5,-1326.33 2257.5,-1123 ; 3524.5,-1733 3524.5,-1123 ; 4413.5,-1733 5989,-1733 5989,-1123 -612.5,-1123 -612.5,-1733 1984.5,-1733 5989.5,-1733 5989.5,-1123
  text "COMPONENTS MARKED 'DNP' SHOULD NOT BE POPULATED." at 5782,-917 h60
  text ".VariantName" at 4738,-1033 h60
  text "ASSEMBLY VARIANT:" at 5777,-1033 h60
  text ".VersionControl_RevNumber" at 715.5,-1255.17 h60
  text "SVN REV:" at 1221.5,-1255.17 h60
  text ".PCB_Rev" at 1768,-1255.17 h60
  text "REV:" at 2059.5,-1255.17 h60
  text ".PRJ_Number" at 2904,-1255.17 h60
  text "BOARD #:" at 3449.5,-1255.17 h60
  text "PCB VIEWED FROM BOTTOM SIDE" at 5926,-1255.17 h60
  text ".Layer_Name" at 5142,-1449 h50
  text ".TID" at 2904,-1458.5 h60
  text "TID #:" at 3449.5,-1458.5 h60
  text "TEXAS INSTRUMENTS" at 584.5,-1663.84 h60
  text ".Print_Time" at 1849,-1663.84 h60
  text ".Print_Date" at 2578,-1663.84 h60
  text "GENERATED    :" at 3447.5,-1663.84 h60
  text ".plot_File_Name" at 5120.5,-1663.84 h60
  text "PLOT NAME =" at 5926,-1663.84 h60
M9 Title Sheet:
  drawing of 57 lines, arcs and shapes, not listed
  text "1" at 419.84,7437.5 h70
  text "2" at 2915.5,7437.5 h70
  text "3" at 5404.84,7437.5 h70
  text "4" at 7911.51,7437.5 h70
  text "5" at 10410.5,7437.5 h70
  text "6" at 12915.5,7437.5 h70
  text "A" at -736.5,6294.5 h70
  text "A" at 14063.5,6294.5 h70
  text "B" at -736.5,3914.5 h70
  text "B" at 14063.5,3914.5 h70
  text "C" at -736.5,1539.5 h70
  text "C" at 14063.5,1539.5 h70
  text "PROJECT TITLE:" at 11023.5,-321.5 h45
  text ".PRJ_Title" at 11073.5,-454.83 h95
  text "DESIGNED FOR:" at 11023.5,-622.5 h45
  text ".PRJ_Customer" at 11073.5,-762.5 h70
  text "D" at -736.5,-830.5 h70
  text "D" at 14063.5,-830.5 h70
  text "FILE NAME:" at 11023.5,-922.5 h45
  text ".PCB_File_Name_No_Path" at 11073.5,-1042.5 h70
  text "Texas Instruments (TI) and/or its licensors do not warrant the accuracy or completeness of this specification" at 6054,-1204.34 h45
  text "ENGINEER:" at 11023.5,-1212.5 h45
  text "LAYOUT BY:" at 12528.5,-1212.5 h45
  text "or any information contained therein. TI and/or its licensors do not warrant that this design will meet" at 6009.01,-1317 h45
  text ".PRJ_Engineer" at 11073.5,-1367.49 h70
  text ".PCB_Layout" at 12579,-1367.49 h70
  text "the specifications, will be suitable for your application or fit for any particular purpose, or will operate in" at 6009.01,-1429.67 h45
  text "ALTIUM DESIGNER VERSION:" at 12528.5,-1522.5 h45
  text "an implementation. TI and/or its licensors do not warrant that the design is production worthy. You should" at 6009.01,-1542.33 h45
  text "completely validate and test your design implementation to confirm the system functionality for your application." at 6054,-1655 h45
  text ".print_Scale" at 11073.5,-1655.83 h70
  text ".Application_BuildNumber" at 12579,-1655.83 h70
  text "1" at 419.84,-1862.5 h70
  text "2" at 2915.5,-1862.5 h70
  text "3" at 5404.84,-1862.5 h70
  text "4" at 7911.51,-1862.5 h70
  text "5" at 10410.5,-1862.5 h70
  text "6" at 12915.5,-1862.5 h70
M10 Fab Notes:
  drawing of 228 lines, arcs and shapes, not listed
  text "DESIGN INFORMATION" at 12055.52,6204 h60
  text "(REFER ALSO ARRAY/PANEL PROFILING INFORMATION)" at 11693.96,6042.29 h60
  text "BOARD SIZE" at 11007.96,6038 h60
  text "60 MM" at 11470.28,5910.18 h60
  text "X" at 11975.96,5910.18 h60
  text "35MM" at 12207.28,5910.18 h60
  text "Number of Layers :" at 11410.96,5713 h60
  text "2" at 12505.77,5703 h60
  text "MIN. TRACK WIDTH:" at 11410.96,5574 h60
  text "8" at 12507.2,5574 h60
  text "MIL" at 12661.96,5574 h60
  text "MIN. CLEARANCE:" at 11410.96,5442 h60
  text "MIL" at 12661.96,5442 h60
  text "8" at 12498.5,5436 h60
  text "7.874" at 12379,5312 h60
  text "MIN. VIA DRILL SIZE:" at 11410.96,5310 h60
  text "MIL" at 12661.96,5310 h60
  text "MINIMUM ANNULAR RING" at 11081.73,5164 h60
  text "0.15mm (5.9 MIL)" at 12148,5162 h60
  text "EXTERNAL" at 13102.5,5162 h60
  text "PER" at 11281.73,5046 h60
  text "IPC-D-275 CLASS 2 LEVEL C" at 11501.73,5046 h60
  text "MIL, HOLES" at 12989.96,4933.71 h60
  text "+/-" at 12597.5,4933 h60
  text "+/-" at 13451.5,4933 h60
  text "REGISTRATION TOLERANCES:" at 11081.73,4928 h60
  text "METAL" at 12281.5,4928 h60
  text "5" at 12857.7,4928 h60
  text "3" at 13690.7,4928 h60
  text "MIL" at 13806.96,4928 h60
  text "MATERIAL:" at 11006.96,4718.54 h60
  text "FR-4 High Tg" at 11993.4,4578.21 h60
  text "FR-408" at 11427.96,4569.64 h60
  text "OTHER" at 12915.96,4569.64 h60
  text "X" at 11837.5,4562 h60
  text "63 MIL (1.6mm) +/-10%" at 11748.06,4406.92 h60
  text "THICKNESS:" at 11081.73,4402.64 h60
  text "X" at 11619.9,4402.64 h60
  text "OTHER" at 13032.96,4402.64 h60
  text "TOLERANCE:" at 11081.73,4244.64 h60
  text "X" at 11921.03,4244.64 h60
  text "ANSI IPC-6012 TYPE 3 CLASS 2" at 12107.98,4244.64 h60
  text "OTHER +/-" at 12107.96,4088.64 h60
  text "BOW & TWIST:" at 11081.73,3931.64 h60
  text "X" at 11921.03,3931.64 h60
  text "ANSI IPC-6012 TYPE 3 CLASS 2" at 12107.98,3931.64 h60
  text "OTHER +/-" at 12107.96,3773.13 h60
  text "COPPER THICKNESS (FINISHED):" at 11006.96,3637.64 h60
  text "1.4MIL (1oz)" at 11886.96,3484.92 h60
  text "2MIL (1.4oz)" at 12653.96,3484.92 h60
  text "2.8MIL (2oz)" at 13380.96,3484.92 h60
  text "OUTER:" at 11363.96,3480.64 h60
  text "X" at 11754,3480 h60
  text "1.4MIL (1oz)" at 11886.96,3327.92 h60
  text "2.8MIL (2oz)" at 12653.96,3327.92 h60
  text "N/A" at 13380.5,3328.29 h60
  text "INNER SIGNAL:" at 11074.88,3323.64 h60
  text "DRILLING:" at 11006.96,3184.64 h60
  text "REFERENCE:" at 11081.73,3067.64 h60
  text "X" at 11729.96,3067.64 h60
  text "AS SHOWN" at 11916.96,3067.64 h60
  text "X" at 12630.96,3067.64 h60
  text "NC_DRILL FILES" at 12767.96,3067.64 h60
  text "PTH MIN COPPER THICKNESS:" at 11081.73,2909.64 h60
  text "X" at 12431.96,2909.64 h60
  text "1MIL" at 12568.96,2909.64 h60
  text "OTHER" at 13065.96,2909.64 h60
  text "BOARD FINISH:" at 11006.96,2750.64 h60
  text "SILKSCREEN:" at 11162.18,2632.64 h60
  text "X" at 12110.96,2632.64 h60
  text "TOP" at 12236.96,2632.64 h60
  text "X" at 12620.96,2632.64 h60
  text "BOTTOM" at 12747.96,2632.64 h60
  text "SILKSCREEN COLOR:" at 11162.18,2465.64 h60
  text "X" at 12109.92,2465.64 h60
  text "WHITE" at 12236.96,2465.64 h60
  text "OTHER" at 12747.96,2465.64 h60
  text "SOLDER RESIST COLOR:" at 11162.18,2295.64 h60
  text "X" at 11729.92,2136.44 h60
  text "GREEN" at 11856.96,2136.44 h60
  text "BLUE" at 12447.96,2136.44 h60
  text "OTHER" at 12985.96,2136.44 h60
  text "IMMERSION GOLD (ENIG)" at 12067.96,1947.92 h60
  text "ENEPIG" at 13405.5,1944.64 h60
  text "SURFACE FINISH:" at 11006.96,1943.64 h60
  text "X" at 11881.01,1943.64 h60
  text "IMM. TIN/SILVER OR EQUIV" at 11336.5,1786.64 h60
  text "OTHER" at 12767.96,1786.64 h60
  text "Note:" at 512,1786 h50
  text "12MIL Vias are Tented in both the sides." at 509,1710 h50
  text "7.874MIL vias are not Tented." at 510,1643 h50
  text "ARRAY/PANEL:" at 11006.96,1607.64 h60
  text "CUT AND TRIM PER MECH LAYER 1" at 12067.96,1603.35 h60
  text "N.C. ROUTE" at 12067.96,1451.64 h60
  text "X" at 12746.96,1451.64 h60
  text "V. SCORE" at 12933.96,1451.64 h60
  text "CERTIFICATION:" at 11006.96,1314.64 h60
  text "MATERIALS AND WORKMANSHIP FOR ALL PCBS" at 11731.96,1314.64 h60
  text "TO MEET OR EXCEED THE REQUIREMENTS OF:" at 11731.96,1216.64 h60
  text "X" at 11358.46,1080.13 h60
  text "ANSI IPC-A-600F CLASS ->" at 11497.46,1080.13 h60
  text "X" at 13136.52,1080.13 h60
  text "2" at 13255.46,1080.14 h60
  text "1" at 12940.46,1078.64 h60
  text "3" at 13609.46,1078.64 h60
  text "X" at 11360.52,920.64 h60
  text "UL 94V-0" at 11497.46,920.64 h60
  text "X" at 12172.52,920.64 h60
  text "RoHS" at 12309.46,920.64 h60
  text "OTHER" at 12953.86,920.64 h60
  text "PER ORDER" at 13350.92,920.64 h60
  text "VIA TENTING:" at 12224.5,787 h60
  text "ADDITIONAL REQUIREMENTS:" at 11006.96,779.64 h60
  text "X" at 12972,779 h60
  text "YES" at 12774.17,777.92 h60
  text "NO" at 13138.97,772.69 h60
  text "MICROSECTION:" at 11081.73,664.64 h60
  text "YES" at 11987.46,664.64 h60
  text "IMPEDANCE CONTROL:" at 12246.5,658 h60
  text "YES" at 13230.5,657 h60
  text "X" at 13767,655 h60
  text "NO" at 13605.97,639.69 h60
  text "REQUIRED" at 12848.96,508.49 h60
  text "BARE BOARD ELEC. TEST:" at 11081.73,505.64 h60
  text "NONE" at 12387.46,505.64 h60
  text "X" at 12721.96,505.64 h60
  text "PER ORDER" at 13440.96,505.64 h60
  text "MANUFACTURER'S UL:" at 11081.73,348.64 h60
  text "RAIL" at 12247.46,344.35 h60
  text "METAL" at 12739.27,344.35 h60
  text "X" at 13114.5,344 h60
  text "SILK" at 13250.96,344.35 h60
M11 Gerber Information:
  lines w10: -612,-1529.17 5988,-1529.17 ; -612,-1325.83 5990,-1325.83 ; -612,-1122.5 -612,-1732.5 3393,-1732.5 5990,-1732.5 5990,-1122.5 -611.5,-1122.5 -611.5,-1732.5 964,-1732.5 ; 1853,-1732.5 1853,-1122.5 ; 3120,-1325.83 3120,-1122.5 ; 3960,-1325.83 3960,-1122.5 ; 4582,-1739 4582,-1536.17
  text "ALL ARTWORK VIEWED FROM TOP SIDE" at -548.5,-1254.67 h60
  text "BOARD #:" at 1928,-1254.67 h60
  text ".PRJ_Number" at 2473.5,-1254.67 h60
  text "REV:" at 3318,-1254.67 h60
  text ".PCB_Rev" at 3609.5,-1254.67 h60
  text "SVN REV:" at 4156,-1254.67 h60
  text ".VersionControl_RevNumber" at 4662,-1254.67 h60
  text "LAYER NAME =" at -548.5,-1457.49 h60
  text "TID #:" at 1928,-1458 h60
  text ".TID" at 2473.5,-1458 h60
  text "PLOT NAME =" at -548.5,-1663.34 h60
  text ".plot_File_Name" at 257,-1663.34 h60
  text "GENERATED    :" at 1930,-1663.34 h60
  text ".Print_Date" at 2799.5,-1663.34 h60
  text ".Print_Time" at 3528.5,-1663.34 h60
  text "TEXAS INSTRUMENTS" at 4793,-1663.34 h60
M12 Stackup:
  drawing of 191 lines, arcs and shapes, not listed
  text "Layer" at 9449,7214 h60
  text "Name" at 9858.91,7214 h60
  text "Material" at 10788.66,7214 h60
  text "Thickness" at 11678.41,7214 h60
  text "Constant" at 12328.25,7214 h60
  text "Board Layer Stack" at 12898.11,7214 h60
  text "1" at 9449,7094 h60
  text "Top Overlay" at 9858.91,7094 h60
  text "2" at 9449,6974 h60
  text "Top Solder" at 9858.91,6974 h60
  text "Solder Resist" at 10788.66,6974 h60
  text "0.40mil" at 11678.41,6974 h60
  text "3.5" at 12328.25,6974 h60
  text "3" at 9449,6854 h60
  text "Top Layer" at 9858.91,6854 h60
  text "Copper" at 10788.66,6854 h60
  text "1.40mil" at 11678.41,6854 h60
  text "4" at 9449,6734 h60
  text "Dielectric1" at 9858.91,6734 h60
  text "FR-4  High Tg" at 10788.66,6734 h60
  text "59.20mil" at 11678.41,6734 h60
  text "4.8" at 12328.25,6734 h60
  text "5" at 9449,6614 h60
  text "Bottom Layer" at 9858.91,6614 h60
  text "Copper" at 10788.66,6614 h60
  text "1.40mil" at 11678.41,6614 h60
  text "6" at 9449,6494 h60
  text "Bottom Solder" at 9858.91,6494 h60
  text "Solder Resist" at 10788.66,6494 h60
  text "0.40mil" at 11678.41,6494 h60
  text "3.5" at 12328.25,6494 h60
  text "7" at 9449,6374 h60
  text "Bottom Overlay" at 9858.91,6374 h60
M13 Component Bodies Top:
  text ".Layer_Name" at 257,-1457.49 h60
M14 Component Bodies Bottom:
  text ".Layer_Name" at 257,-1457.49 h60
M15 Courtyards Top:
  text ".Layer_Name" at 257,-1457.49 h60
M16 Courtyards Bottom:
  text ".Layer_Name" at 257,-1457.49 h60
Drill Drawing:
  drawing of 152 lines, arcs and shapes, not listed
  text "Symbol" at 564,5439 h72
  text "Hit Count" at 1069.88,5439 h72
  text "Finished Hole Size" at 1767.69,5439 h72
  text "Plated" at 3113.29,5439 h72
  text "Hole Type" at 3619.17,5439 h72
  text "Physical Length" at 4352.97,5439 h72
  text "Rout Path Length" at 5682.58,5439 h72
  text "1" at 1069.88,5289 h60
  text "20.00mil (0.50800mm)" at 1767.69,5289 h60
  text "NPTH" at 3113.29,5289 h60
  text "Slot" at 3619.17,5289 h60
  text "50.00mil (1.27000mm)" at 4352.97,5289 h60
  text "30.00mil (0.76200mm)" at 5682.58,5289 h60
  text "1" at 1069.88,5139 h60
  text "20.00mil (0.50800mm)" at 1767.69,5139 h60
  text "NPTH" at 3113.29,5139 h60
  text "Slot" at 3619.17,5139 h60
  text "100.00mil (2.54000mm)" at 4352.97,5139 h60
  text "80.00mil (2.03200mm)" at 5682.58,5139 h60
  text "F" at 554.62,5001.5 h50
  text "1" at 1069.88,4989 h60
  text "20.00mil (0.50800mm)" at 1767.69,4989 h60
  text "NPTH" at 3113.29,4989 h60
  text "Slot" at 3619.17,4989 h60
  text "115.00mil (2.92100mm)" at 4352.97,4989 h60
  text "95.00mil (2.41300mm)" at 5682.58,4989 h60
  text "G" at 554.62,4851.5 h50
  text "1" at 1069.88,4839 h60
  text "20.00mil (0.50800mm)" at 1767.69,4839 h60
  text "NPTH" at 3113.29,4839 h60
  text "Slot" at 3619.17,4839 h60
  text "135.00mil (3.42900mm)" at 4352.97,4839 h60
  text "115.00mil (2.92100mm)" at 5682.58,4839 h60
  text "B" at 554.62,4701.5 h50
  text "1" at 1069.88,4689 h60
  text "20.00mil (0.50800mm)" at 1767.69,4689 h60
  text "NPTH" at 3113.29,4689 h60
  text "Slot" at 3619.17,4689 h60
  text "250.00mil (6.35000mm)" at 4352.97,4689 h60
  text "230.00mil (5.84200mm)" at 5682.58,4689 h60
  text "I" at 554.62,4551.5 h50
  text "1" at 1069.88,4539 h60
  text "20.00mil (0.50800mm)" at 1767.69,4539 h60
  text "NPTH" at 3113.29,4539 h60
  text "Slot" at 3619.17,4539 h60
  text "274.02mil (6.96000mm)" at 4352.97,4539 h60
  text "254.02mil (6.45200mm)" at 5682.58,4539 h60
  text "1" at 1069.88,4389 h60
  text "20.00mil (0.50800mm)" at 1767.69,4389 h60
  text "NPTH" at 3113.29,4389 h60
  text "Slot" at 3619.17,4389 h60
  text "400.00mil (10.16000mm)" at 4352.97,4389 h60
  text "380.00mil (9.65200mm)" at 5682.58,4389 h60
  text "1" at 1069.88,4239 h60
  text "20.00mil (0.50800mm)" at 1767.69,4239 h60
  text "NPTH" at 3113.29,4239 h60
  text "Slot" at 3619.17,4239 h60
  text "500.00mil (12.70000mm)" at 4352.97,4239 h60
  text "480.00mil (12.19200mm)" at 5682.58,4239 h60
  text "E" at 554.62,4101.5 h50
  text "2" at 1069.88,4089 h60
  text "40.00mil (1.01600mm)" at 1767.69,4089 h60
  text "NPTH" at 3113.29,4089 h60
  text "Round" at 3619.17,4089 h60
  text "2" at 1069.88,3939 h60
  text "45.67mil (1.16000mm)" at 1767.69,3939 h60
  text "PTH" at 3113.29,3939 h60
  text "Round" at 3619.17,3939 h60
  text "2" at 1069.88,3789 h60
  text "82.00mil (2.08300mm)" at 1767.69,3789 h60
  text "PTH" at 3113.29,3789 h60
  text "Round" at 3619.17,3789 h60
  text "3" at 1069.88,3639 h60
  text "50.00mil (1.27000mm)" at 1767.69,3639 h60
  text "PTH" at 3113.29,3639 h60
  text "Round" at 3619.17,3639 h60
  text "4" at 1069.88,3489 h60
  text "7.87mil (0.20000mm)" at 1767.69,3489 h60
  text "PTH" at 3113.29,3489 h60
  text "Round" at 3619.17,3489 h60
  text "4" at 1069.88,3339 h60
  text "35.43mil (0.90000mm)" at 1767.69,3339 h60
  text "PTH" at 3113.29,3339 h60
  text "Round" at 3619.17,3339 h60
  text "4" at 1069.88,3189 h60
  text "39.37mil (1.00000mm)" at 1767.69,3189 h60
  text "PTH" at 3113.29,3189 h60
  text "Round" at 3619.17,3189 h60
  text "8" at 1069.88,3039 h60
  text "40.00mil (1.01600mm)" at 1767.69,3039 h60
  text "PTH" at 3113.29,3039 h60
  text "Round" at 3619.17,3039 h60
  text "14" at 1069.88,2889 h60
  text "51.97mil (1.32000mm)" at 1767.69,2889 h60
  text "PTH" at 3113.29,2889 h60
  text "Round" at 3619.17,2889 h60
  text "16" at 1069.88,2739 h60
  text "33.46mil (0.85000mm)" at 1767.69,2739 h60
  text "PTH" at 3113.29,2739 h60
  text "Round" at 3619.17,2739 h60
  text "45" at 1069.88,2589 h60
  text "12.00mil (0.30500mm)" at 1767.69,2589 h60
  text "PTH" at 3113.29,2589 h60
  text "Round" at 3619.17,2589 h60
  text "112 Total" at 1069.88,2439 h60
  text "Drill Table" at 517,2243 h60
  text "FOR 7.874MIL DRILL +0/-7.874MIL" at 513,2162 h60
  text "FOR 12MIL DRILL +0/-12MIL" at 513,2065 h60
  text "FOR PTH DRILL +/-3MIL" at 513,1957 h60
  text "FOR NPTH DRILL +/-2MIL" at 508,1856 h60
  text ".Layer_Name" at 257,-1457.49 h60

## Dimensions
-320,-999 to 680,-999 on M2 Board Dimensions
0,1377.95 to 0,0 on M2 Board Dimensions
0,0 to 2362.2,0 on M2 Board Dimensions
